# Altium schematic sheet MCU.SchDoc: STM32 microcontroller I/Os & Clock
size A4; Date: Not used; ApprovedBy: Not used; CheckedBy: Not used; Author: Not used; CompanyName: STMicroelectronics; DrawnBy: Not used; Engineer: Not used; Organization: Not used; Address1: Not used; Address2: Not used; Address3: Not used; Address4: Not used; DocumentNumber: 3; Revision: Not used; SheetNumber: 3; SheetTotal: 4
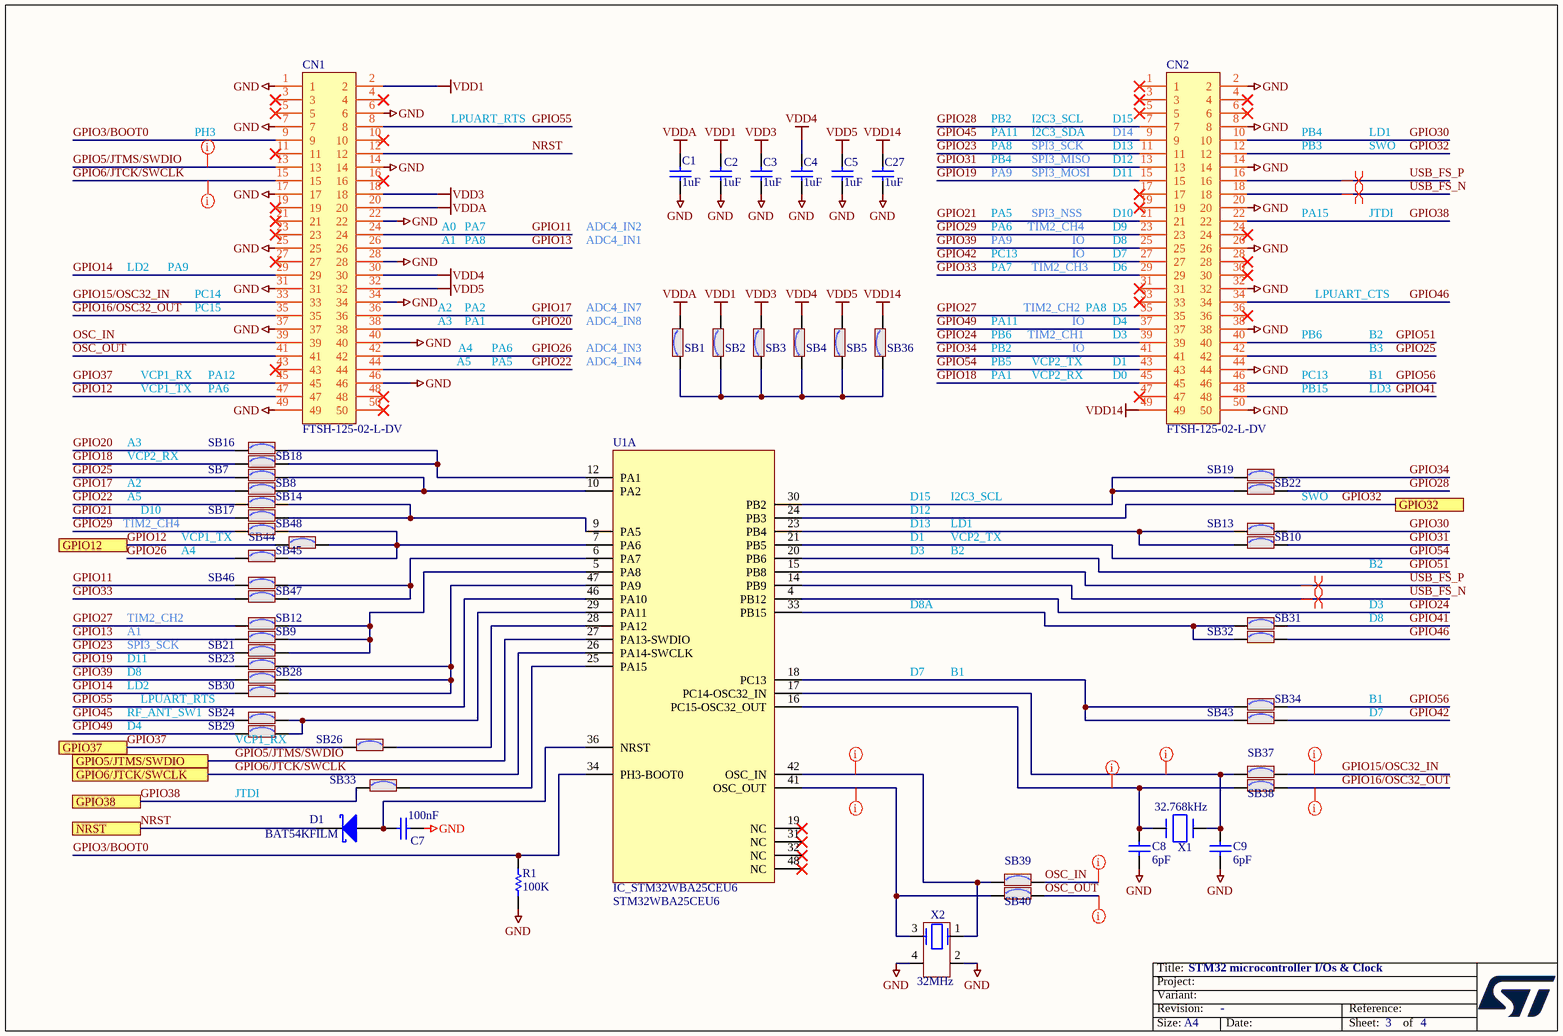
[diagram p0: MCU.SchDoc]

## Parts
C1  value 1uF  [C0402]  (hidden comment: Capacitor)
C2  value 1uF  [C0402]  (hidden comment: Capacitor)
C3  value 1uF  [C0402]  (hidden comment: Capacitor)
C4  value 1uF  [C0402]  (hidden comment: Capacitor)
C5  value 1uF  [C0402]  (hidden comment: Capacitor)
C7  value 100nF  [C0402]  (hidden comment: Capacitor)
C8  value 6pF  [C0402]  (hidden comment: Capacitor)
C9  value 6pF  [C0402]  (hidden comment: Capacitor)
C27  value 1uF  [C0402]  (hidden comment: Capacitor)
CN1  FTSH-125-02-L-DV  [Footprint sent by email... (Footprint FTSH-125-02-L-DV)]
CN2  FTSH-125-02-L-DV  [Footprint sent by email... (Footprint FTSH-125-02-L-DV)]
D1  value BAT54KFILM  [DIO_SOD523_1A_2K]  (hidden comment: SCHOTTKY_1A_2K)
R1  value 100K  [R0402]  (hidden comment: Resistor)
SB1  SB_ON  [SOLDER-BRIDGE_R0402-0R]  (value not drawn)
SB2  SB_ON  [SOLDER-BRIDGE_R0402-0R]  (value not drawn)
SB3  SB_ON  [SOLDER-BRIDGE_R0402-0R]  (value not drawn)
SB4  SB_ON  [SOLDER-BRIDGE_R0402-0R]  (value not drawn)
SB5  SB_ON  [SOLDER-BRIDGE_R0402-0R]  (value not drawn)
SB7  SB_ON  [SOLDER-BRIDGE_R0402-0R]  (value not drawn)
SB8  SB_ON  [SOLDER-BRIDGE_R0402-0R]  (value not drawn)
SB9  SB_ON  [SOLDER-BRIDGE_R0402-0R]  (value not drawn)
SB10  SB_ON  [SOLDER-BRIDGE_R0402-0R]  (value not drawn)
SB12  SB_ON  [SOLDER-BRIDGE_R0402-0R]  (value not drawn)
SB13  SB_ON  [SOLDER-BRIDGE_R0402-0R]  (value not drawn)
SB14  SB_ON  [SOLDER-BRIDGE_R0402-0R]  (value not drawn)
SB16  SB_ON  [SOLDER-BRIDGE_R0402-0R]  (value not drawn)
SB17  SB_ON  [SOLDER-BRIDGE_R0402-0R]  (value not drawn)
SB18  SB_ON  [SOLDER-BRIDGE_R0402-0R]  (value not drawn)
SB19  SB_ON  [SOLDER-BRIDGE_R0402-0R]  (value not drawn)
SB21  SB_ON  [SOLDER-BRIDGE_R0402-0R]  (value not drawn)
SB22  SB_ON  [SOLDER-BRIDGE_R0402-0R]  (value not drawn)
SB23  SB_ON  [SOLDER-BRIDGE_R0402-0R]  (value not drawn)
SB24  SB_ON  [SOLDER-BRIDGE_R0402-0R]  (value not drawn)
SB26  SB_ON  [SOLDER-BRIDGE_R0402-0R]  (value not drawn)
SB28  SB_ON  [SOLDER-BRIDGE_R0402-0R]  (value not drawn)
SB29  SB_ON  [SOLDER-BRIDGE_R0402-0R]  (value not drawn)
SB30  SB_ON  [SOLDER-BRIDGE_R0402-0R]  (value not drawn)
SB31  SB_ON  [SOLDER-BRIDGE_R0402-0R]  (value not drawn)
SB32  SB_ON  [SOLDER-BRIDGE_R0402-0R]  (value not drawn)
SB33  SB_ON  [SOLDER-BRIDGE_R0402-0R]  (value not drawn)
SB34  SB_ON  [SOLDER-BRIDGE_R0402-0R]  (value not drawn)
SB36  SB_ON  [SOLDER-BRIDGE_R0402-0R]  (value not drawn)
SB37  SB_ON  [SOLDER-BRIDGE_R0402-0R]  (value not drawn)
SB38  SB_ON  [SOLDER-BRIDGE_R0402-0R]  (value not drawn)
SB39  SB_ON  [SOLDER-BRIDGE_R0402-0R]  (value not drawn)
SB40  SB_ON  [SOLDER-BRIDGE_R0402-0R]  (value not drawn)
SB43  SB_ON  [SOLDER-BRIDGE_R0402-0R]  (value not drawn)
SB44  SB_ON  [SOLDER-BRIDGE_R0402-0R]  (value not drawn)
SB45  SB_ON  [SOLDER-BRIDGE_R0402-0R]  (value not drawn)
SB46  SB_ON  [SOLDER-BRIDGE_R0402-0R]  (value not drawn)
SB47  SB_ON  [SOLDER-BRIDGE_R0402-0R]  (value not drawn)
SB48  SB_ON  [SOLDER-BRIDGE_R0402-0R]  (value not drawn)
U1  IC_STM32WBA25CEU6  value STM32WBA25CEU6  [ICC_UFQFPN48-EPAD_7X7_H0P55_P050]  (part A of 3)
X1  value 32.768kHz  [CRY_NX1610SE_2P]  (hidden comment: XTAL_2_PINS)
X2  value 32MHz  [CRY_NX1612SA_4P]  (hidden comment: XTAL_4_PINS)

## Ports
GPIO5/JTMS/SWDIO, GPIO6/JTCK/SWCLK, GPIO12, GPIO32, GPIO37, GPIO38, NRST

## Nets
GND: C1.1 C2.1 C3.1 C4.1 C5.1 C7.1 C8.2 C9.1 C27.1 CN1.1 CN1.6 CN1.7 CN1.14 CN1.17 CN1.22 CN1.25 CN1.28 CN1.31 CN1.34 CN1.37 CN1.40 CN1.46 CN1.49 CN2.2 CN2.8 CN2.14 CN2.20 CN2.26 CN2.32 CN2.38 CN2.44 CN2.50 R1.2 X2.2 X2.4
VDD1: C2.2 CN1.2 SB2.2
VDD3: C3.2 CN1.18 SB3.2
VDD4: C4.2 CN1.30 SB4.2
VDD5: C5.2 CN1.32 SB5.2
VDD14: C27.2 CN2.49 SB36.2
VDDA: C1.2 CN1.20 SB1.2
GPIO3/BOOT0: CN1.9 R1.1 U1.34(PH3-BOOT0)
GPIO5/JTMS/SWDIO: CN1.13 U1.27(PA13-SWDIO) ; port GPIO5/JTMS/SWDIO
GPIO6/JTCK/SWCLK: CN1.15 U1.26(PA14-SWCLK) ; port GPIO6/JTCK/SWCLK
GPIO11: CN1.24 SB46.1
GPIO12: CN1.47 SB44.1 ; port GPIO12
GPIO13: CN1.26 SB9.1
GPIO14: CN1.29 SB30.1
GPIO15/OSC32_IN: CN1.33 SB37.2
GPIO16/OSC32_OUT: CN1.35 SB38.2
GPIO17: CN1.36 SB8.1
GPIO18: CN2.45 SB18.1
GPIO19: CN2.15 SB23.1
GPIO20: CN1.38 SB16.1
GPIO21: CN2.21 SB17.1
GPIO22: CN1.44 SB14.1
GPIO23: CN2.11 SB21.1
GPIO24: CN2.39 U1.4(PB12)
GPIO25: CN2.42 SB7.1
GPIO26: CN1.42 SB45.1
GPIO27: CN2.35 SB12.1
GPIO28: CN2.7 SB22.2
GPIO29: CN2.23 SB48.1
GPIO30: CN2.10 SB13.2
GPIO31: CN2.13 SB10.2
GPIO32: CN2.12 U1.24(PB3) ; port GPIO32
GPIO33: CN2.29 SB47.1
GPIO34: CN2.41 SB19.2
GPIO37: CN1.45 SB26.1 ; port GPIO37
GPIO38: CN2.22 SB33.1 ; port GPIO38
GPIO39: CN2.25 SB28.1
GPIO41: CN2.48 SB31.2
GPIO42: CN2.27 SB43.2
GPIO45: CN2.9 SB24.1
GPIO46: CN2.34 SB32.2
GPIO49: CN2.37 SB29.1
GPIO51: CN2.40 U1.20(PB6)
GPIO54: CN2.43 U1.21(PB5)
GPIO55: CN1.8 U1.46(PA10)
GPIO56: CN2.46 SB34.2
NRST: CN1.12 D1.2(K) ; port NRST
OSC_IN: CN1.39 SB39.2
OSC_OUT: CN1.41 SB40.2
USB_FS_N: CN2.18 U1.14(PB9)
USB_FS_P: CN2.16 U1.15(PB8)
NetC7_2: C7.2 D1.1(A) U1.36(NRST)
NetC8_1: C8.1 SB38.1 U1.16(PC15-OSC32_OUT) X1.2(X2)
NetC9_2: C9.2 SB37.1 U1.17(PC14-OSC32_IN) X1.1(X1)
NetSB1_1: SB1.1 SB2.1 SB3.1 SB4.1 SB5.1 SB36.1
NetSB7_2: SB7.2 SB8.2 U1.10(PA2)
NetSB9_2: SB9.2 SB12.2 SB21.2 U1.5(PA8)
NetSB10_1: SB10.1 SB13.1 U1.23(PB4)
NetSB14_2: SB14.2 SB17.2 U1.9(PA5)
NetSB16_2: SB16.2 SB18.2 U1.12(PA1)
NetSB19_1: SB19.1 SB22.1 U1.30(PB2)
NetSB23_2: SB23.2 SB28.2 SB30.2 U1.47(PA9)
NetSB24_2: SB24.2 SB29.2 U1.29(PA11)
NetSB26_2: SB26.2 U1.28(PA12)
NetSB31_1: SB31.1 SB32.1 U1.33(PB15)
NetSB33_2: SB33.2 U1.25(PA15)
NetSB34_1: SB34.1 SB43.1 U1.18(PC13)
NetSB39_1: SB39.1 U1.42(OSC_IN) X2.1
NetSB40_1: SB40.1 U1.41(OSC_OUT) X2.3
NetSB44_2: SB44.2 SB45.2 SB48.2 U1.7(PA6)
NetSB46_2: SB46.2 SB47.2 U1.6(PA7)

Not connected (* = marked no-connect by the designer): CN1 3* 4* 5* 10* 11* 16* 19* 21* 23* 27* 43* 48* 50*; CN2 1* 3* 4* 5* 6* 17* 19* 24* 28* 30* 31* 33* 36* 47*; U1 19(NC)* 31(NC)* 32(NC)* 48(NC)*

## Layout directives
net class X2: NetSB39_1, NetSB40_1, OSC_IN, OSC_OUT
net class X1: GPIO15/OSC32_IN, GPIO16/OSC32_OUT, NetC8_1, NetC9_2
net class SWCLK: GPIO6/JTCK/SWCLK
net class SWDIO: GPIO5/JTMS/SWDIO
differential pair: USB_FS_N, USB_FS_P
differential pair; net class DIFF90: USB_FS_N, USB_FS_P

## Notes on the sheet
- PH3
- LPUART_RTS
- PA8
- PB2
- PB4
- PA11
- PA9
- I2C3_SDA
- I2C3_SCL
- SPI3_SCK
- SPI3_MISO
- SPI3_MOSI
- (near CN2) D11
- (near CN2) D13
- (near CN2) D15
- (near CN2) D12
- (near CN2) D14
- PB3
- SWO
- LD1
- A0
- A1
- PA7
- ADC4_IN2
- ADC4_IN1
- PA5
- PA6
- TIM2_CH4
- SPI3_NSS
- IO
- (near CN2) D10
- (near CN2) D9
- (near CN2) D8
- PA15
- JTDI
- LD2
- PC14
- PC15
- A2
- PA2
- (near SB1) ADC4_IN7
- PC13
- TIM2_CH2
- TIM2_CH3
- (near CN2) D7
- (near CN2) D5
- (near CN2) D6
- LPUART_CTS
- VCP1_RX
- PA12
- A3
- A5
- A4
- PA1
- (near SB1) ADC4_IN8
- (near SB1) ADC4_IN4
- (near SB1) ADC4_IN3
- PB5
- PB6
- TIM2_CH1
- VCP2_TX
- VCP2_RX
- (near CN2) D1
- (near CN2) D4
- (near CN2) D3
- (near CN2) D0
- B1
- B2
- B3
- VCP1_TX
- PB15
- LD3
- D10
- D12
- D15
- D3
- D1
- D13
- D8A
- D8
- RF_ANT_SW1
- D11
- D7
- D4
- (near SB29) VCP1_RX

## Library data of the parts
C1-C5 C27 = MCD-01722: Capacitor, MLCC, 1uF, 10V, X5R, +/-10%, 0402, T=0.5mm; Part_Preference: Recommended; Manufacturer: YAGEO; Manufacturer_Part_Number: CC0402KRX5R6BB105; Component_Country_Of_Origin: China
C7 = MCD-00006: Capacitor, MLCC, 100nF, 16V, X7R, +/-10%, 0402, T=0.5mm; Manufacturer_Part_Number: CC0402KRX7R7BB104; Manufacturer: YAGEO; Alternate_Manufacturer_Part_Number: GCM155R71C104KA55D; Alternate_Manufacturer: MURATA; Part_Preference: Recommended; Order_Code_RS: 616-9701
C8 C9 = MCD-03185: Capacitor, MLCC, 6 pF, 50V, NPO, ±0,25pF, 0402, T=0.5mm; Part_Preference: Recommended; Manufacturer: MURATA; Manufacturer_Part_Number: GJM1555C1H6R0CB01; Order_Code_RS: 170-6040; ShowFields: YES; ID: 5301
CN1 CN2 = MCD-02746: Header 25x2, 12.7mm, SMT,height 4.83mm; Part_Type: Connector; Part_Preference: Recommended; Manufacturer: SAMTEC; Order_code_RS: NA; ShowFields: YES; ID: 4858
D1 = MCD-01677: Small signal Schottky diodes; Part_Type: Diode; Manufacturer: STMICROELECTRONICS; BMS_Part_Number: 9151123; Part_Preference: Recommended; Manufacturer_HQ_COO: EU
R1 = MCD-00059: Resistor, 100K, 0402, +/-1%, 1/16W; Part_Preference: Recommended; Manufacturer: YAGEO; Manufacturer_Part_Number: RC0402FR-07100KL; Component_Country_Of_Origin: China
SB1-SB5 SB7-SB10 SB12-SB14 SB16-SB19 SB21-SB24 SB26 SB28-SB34 SB36-SB40 SB43-SB48 = MCD-01618: Solder Bridge 0402 ON; Part_Type: Misc; Part_Preference: Recommended; Manufacturer: YAGEO; Manufacturer_Part_Number: RC0402JR-070RL; Order_Code_RS: 618-5804; Component_Country_Of_Origin: China
U1 = MCD-04232: MCU, ARM Cortex-M33 32-bit, 512KB Flash, 96KB RAM, Crypto; Part_Type: IC; Part_Preference: Recommended; Manufacturer: STMICROELECTRONICS; Component_Country_Of_Origin: Unknown; ShowFields: YES; ID: 6348
X1 = MCD-02579: Crystal, 32.768kHz, 6pF, +/-20ppm, 70KR, 1.6x1mm; Part_Type: Crystal_Osc; Part_Preference: Recommended; Manufacturer: NDK; Manufacturer_Part_Number: NX1610SE-32.768KHZ-EXS00A-MU01501
X2 = MCD-02578: Crystal, 32MHz, 8pF, +/-10ppm, 40R, 1612(metric), T=0.3mm; Part_Type: Crystal_Osc; Part_Preference: Recommended; Manufacturer: NDK; Manufacturer_Part_Number: NX1612SA-32MHZ-EXS00A-CS09166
